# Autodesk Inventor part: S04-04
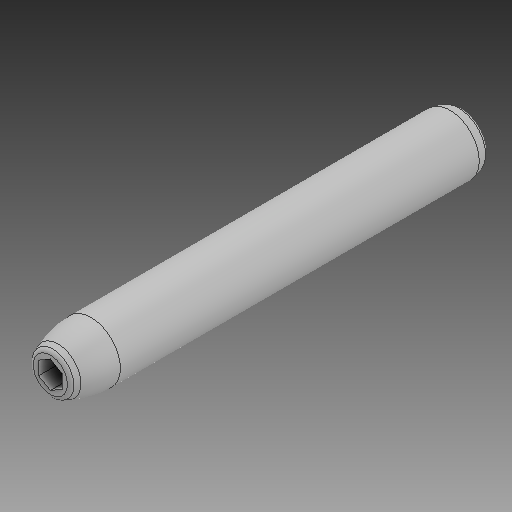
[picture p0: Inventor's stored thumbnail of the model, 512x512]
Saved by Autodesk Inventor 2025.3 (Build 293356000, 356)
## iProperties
Created: 2025-05
Part Number: S04-04
Material: Všeobecné
Document SubType Name: Modeling
Designer: Patrik
Density: 1 g/cm^3
Appearance: Výchozí
Mass: 4.92571 g
Surface Area: 26.3467 cm^2
Volume: 4.92571 cm^3
Description: Šikmý kolík bez nákružku
Stock Number: E 1034/10x70
User Status: 1.7131
Sending System: KiM GmbH
Major Version: 4.0
Minor Version: 0.0
Format Version: 0.0
Product Id: KiM GmbH
cc_prop_force_one_body: 1
Hersteller: Meusburger
Material: 1.7131 ~ 60 HRC
Bestellnummer: E 1034/10x70
Teilenummer: E 1034/10x70
Beschreibung: Schrägbolzen ohne Bund _ Inclined pin without collar
Author: Patrik
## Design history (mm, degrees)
feature "E 1034_10x70_1_1:1"
node "Těleso1"
